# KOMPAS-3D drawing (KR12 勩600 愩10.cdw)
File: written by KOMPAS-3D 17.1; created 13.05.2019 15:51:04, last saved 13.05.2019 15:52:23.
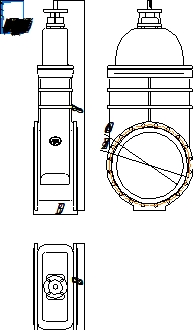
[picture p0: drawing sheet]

Sheet 1: A4, portrait

Title block, sheet 1: name: KR12 Ду600 Ру10; material: Внимание! Данный продукт является объектом авторского права ООО «Торговый Дом АДЛ». / Запрещается изменение, копирование, распространение / (в том числе путем копирования на другие сайты и ресурсы в Интернете) / или любое иное использование информации и объектов без предварительного / согласия правообладателя (ООО «Торговый Дом АДЛ»).; sheets: 1; organisation: ООО "Торговый дом АДЛ"; sheet format: A4

Views: Вид 1, Проекционный вид 2, Проекционный вид 3
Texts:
  user
Dimensions and other numbers on the sheet: 390; 1877; 600; 780; 725; 1:1; 1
